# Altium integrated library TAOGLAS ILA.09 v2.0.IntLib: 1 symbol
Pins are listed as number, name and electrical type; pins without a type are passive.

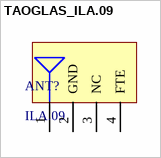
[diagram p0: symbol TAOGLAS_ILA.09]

## TAOGLAS_ILA.09
designator ANT?, comment ILA.09
915MHz Embedded Ceramic Loop Antenna for ISM/Lora/LPWAN/Sigfox; ComponentLibStatus: Created; MFG: Taoglas; Temp_High: +85C; Temp_Low: -40C
footprint TAOGLAS_ILA.09 (915MHz Embedded Ceramic Loop Antenna for ISM/Lora/LPWAN/Sigfox)
pins: 1 RF OUT, 2 GND, 3 NC, 4 FTE "GND"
